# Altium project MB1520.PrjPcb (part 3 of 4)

## Sheet PoE.SchDoc: PoE
size A4; Date: Not used; ApprovedBy: Not used; CheckedBy: Not used; Author: Not used; CompanyName: STMicroelectronics; DrawnBy: Not used; Engineer: Not used; Organization: Not used; Address1: Not used; Address2: Not used; Address3: Not used; Address4: Not used; DocumentNumber: Not used; Revision: Not used; SheetNumber: 6; SheetTotal: 19
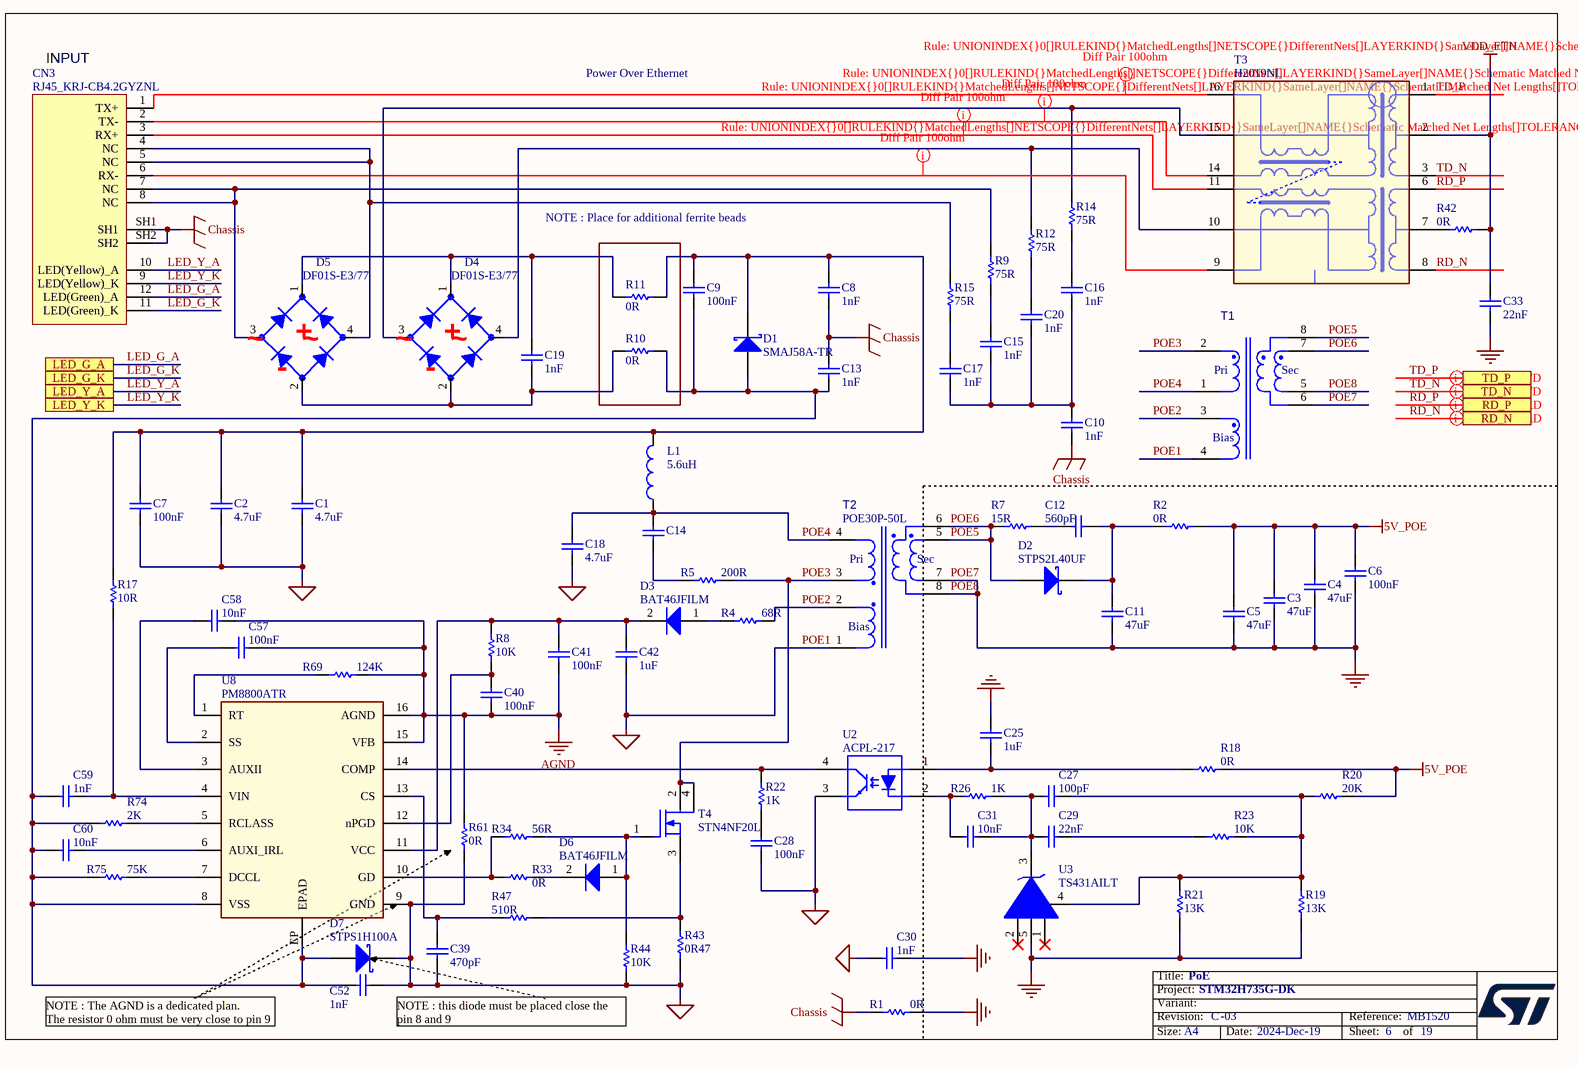
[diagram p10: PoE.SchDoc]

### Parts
C1  value 4.7uF  [C1210_H2P5]  (hidden comment: Capacitor)
C2  value 4.7uF  [C1210_H2P5]  (hidden comment: Capacitor)
C3  value 47uF  [C0805]  (hidden comment: Capacitor)
C4  value 47uF  [C0805]  (hidden comment: Capacitor)
C5  value 47uF  [C0805]  (hidden comment: Capacitor)
C6  value 100nF  [C0603]  (hidden comment: Capacitor)
C7  value 100nF  [C0805]  (hidden comment: Capacitor)
C8  value 1nF  [C0603]  (hidden comment: Capacitor)
C9  value 100nF  [C0805]  (hidden comment: Capacitor)
C10  value 1nF  [C1206_H1P6]  (hidden comment: Capacitor)
C11  value 47uF  [C0805]  (hidden comment: Capacitor)
C12  value 560pF  [C0603]  (hidden comment: Capacitor)
C13  value 1nF  [C0603]  (hidden comment: Capacitor)
C14  Capacitor  [C0603]  (value not drawn)
C15  value 1nF  [C0603]  (hidden comment: Capacitor)
C16  value 1nF  [C0603]  (hidden comment: Capacitor)
C17  value 1nF  [C0603]  (hidden comment: Capacitor)
C18  value 4.7uF  [C1210_H2P5]  (hidden comment: Capacitor)
C19  value 1nF  [C0603]  (hidden comment: Capacitor)
C20  value 1nF  [C0603]  (hidden comment: Capacitor)
C25  value 1uF  [C0603]  (hidden comment: Capacitor)
C27  value 100pF  [C0603]  (hidden comment: Capacitor)
C28  value 100nF  [C0603]  (hidden comment: Capacitor)
C29  value 22nF  [C0603]  (hidden comment: Capacitor)
C30  value 1nF  [C1206_H1P6]  (hidden comment: Capacitor)
C31  value 10nF  [C0603]  (hidden comment: Capacitor)
C33  value 22nF  [C0603]  (hidden comment: Capacitor)
C39  value 470pF  [C0603]  (hidden comment: Capacitor)
C40  value 100nF  [C0603]  (hidden comment: Capacitor)
C41  value 100nF  [C0603]  (hidden comment: Capacitor)
C42  value 1uF  [C0603]  (hidden comment: Capacitor)
C52  value 1nF  [C0603]  (hidden comment: Capacitor)
C57  value 100nF  [C0603]  (hidden comment: Capacitor)
C58  value 10nF  [C0603]  (hidden comment: Capacitor)
C59  value 1nF  [C0603]  (hidden comment: Capacitor)
C60  value 10nF  [C0603]  (hidden comment: Capacitor)
CN3  RJ45_KRJ-CB4.2GYZNL  [CON_RJ45_DGKYD_KRJ-CB4.2GYZNL]
D1  SMAJ58A-TR  [DIO_SMA_1A_2K]
D2  STPS2L40UF  [DIO_SMB-FLAT_1A_2K]
D3  value BAT46JFILM  [DIO_SOD323_1A_2K]  (hidden comment: DIODE_1A_2K)
D4  value DF01S-E3/77  [BRF_VISHAY_DFS_DF01S]  (hidden comment: DF01S_SMD)
D5  value DF01S-E3/77  [BRF_VISHAY_DFS_DF01S]  (hidden comment: DF01S_SMD)
D6  value BAT46JFILM  [DIO_SOD323_1A_2K]  (hidden comment: DIODE_1A_2K)
D7  value STPS1H100A  [DIO_SMA_DO214-AC_1A_2K]  (hidden comment: SMAJ58A-TR)
L1  value 5.6uH  [IND_POWER_COILCRAFT_ME3220]  (hidden comment: Inductor)
R1  value 0R  [R0805]  (hidden comment: Resistor)
R2  value 0R  [R0603]  (hidden comment: Resistor)
R4  value 68R  [R0805]  (hidden comment: Resistor)
R5  value 200R  [R1206_H0P55]  (hidden comment: Resistor)
R7  value 15R  [R0805]  (hidden comment: Resistor)
R8  value 10K  [R0603]  (hidden comment: Resistor)
R9  value 75R  [R0805]  (hidden comment: Resistor)
R10  value 0R  [R0805]  (hidden comment: Resistor)
R11  value 0R  [R0805]  (hidden comment: Resistor)
R12  value 75R  [R0805]  (hidden comment: Resistor)
R14  value 75R  [R0805]  (hidden comment: Resistor)
R15  value 75R  [R0805]  (hidden comment: Resistor)
R17  value 10R  [R0805]  (hidden comment: Resistor)
R18  value 0R  [R0805]  (hidden comment: Resistor)
R19  value 13K  [R0603]  (hidden comment: Resistor)
R20  value 20K  [R0603]  (hidden comment: Resistor)
R21  value 13K  [R0603]  (hidden comment: Resistor)
R22  value 1K  [R0603]  (hidden comment: Resistor)
R23  value 10K  [R0603]  (hidden comment: Resistor)
R26  value 1K  [R0603]  (hidden comment: Resistor)
R33  value 0R  [R0805]  (hidden comment: Resistor)
R34  value 56R  [R0805]  (hidden comment: Resistor)
R42  value 0R  [R0805]  (hidden comment: Resistor)
R43  value 0R47  [R1206_H0P55]  (hidden comment: Resistor)
R44  value 10K  [R0603]  (hidden comment: Resistor)
R47  value 510R  [R0603]  (hidden comment: Resistor)
R61  value 0R  [R0603]  (hidden comment: Resistor)
R69  value 124K  [R0603]  (hidden comment: Resistor)
R74  value 2K  [R0805]  (hidden comment: Resistor)
R75  value 75K  [R0603]  (hidden comment: Resistor)
T1  TRS_750315923  [TRS_WURTH_750315923]  (value not drawn)
T2  POE30P-50L  [TRS_COILCRAFT_POE30P-50L]
T3  H2019NL  [TRS_PULSE_H2019NL]
T4  STN4NF20L  [MOS_SOT223-TAB]
U2  value ACPL-217  [OPT_MINI-FLAT_FAIRCHILD_HMHA2801A]  (hidden comment: HMHA2801A)
U3  TS431AILT  [MOS_SOT23-5L]
U8  PM8800ATR  [ICC_HTSSOP16-EPAD_5X4P4_P065]

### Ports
LED_G_A, LED_G_K, LED_Y_A, LED_Y_K, RD_N, RD_P, TD_N, TD_P

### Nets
5V_POE: C3.2 C4.2 C5.2 C6.2 R2.2 R18.2 R20.2
AGND: C40.1 C41.1 C57.2 C58.2 R61.2 R69.2 U8.15(VFB) U8.16(AGND)
Chassis: C8.1 C10.1 C13.2 CN3.SH1 CN3.SH2 R1.1
POE1: C1.1 C2.1 C7.1 C18.1 C28.1 C30.1 C39.1 C42.1 C52.1 D7.2(K) R43.1 R44.1 R61.1 T1.4 T2.1 U2.3(Emitter) U8.9(GND)  [also labelled GND_POWER_IN]
POE7: C3.1 C4.1 C5.1 C6.1 C11.1 C25.2 C30.2 C33.1 R1.2 R19.2 R21.1 T1.5 T1.6 T2.7 T2.8 U3.5(A)  [also labelled GND, POE8]
VDD_ETH: C33.2 R42.2 T3.2(tct)
LED_G_A: CN3.12(LED(Green)_A) ; port LED_G_A
LED_G_K: CN3.11(LED(Green)_K) ; port LED_G_K
LED_Y_A: CN3.10(LED(Yellow)_A) ; port LED_Y_A
LED_Y_K: CN3.9(LED(Yellow)_K) ; port LED_Y_K
POE2: R4.2 T1.3 T2.2
POE3: R5.2 T1.2 T2.3 T4.2(D) T4.4(D)
POE4: C14.2 C18.2 L1.1 T1.1 T2.4
POE5: D2.1(A) R7.1 T1.7 T1.8 T2.5 T2.6  [also labelled POE6]
RD_N: T3.8(rd-) ; port RD_N
RD_P: T3.6(rd+) ; port RD_P
TD_N: T3.3(td-) ; port TD_N
TD_P: T3.1(td+) ; port TD_P
NetC1_2: C1.2 C2.2 C7.2 C8.2 C9.1 D1.2(K) L1.2 R11.2 R17.2
NetC9_2: C9.2 C13.1 C52.2 C59.2 C60.1 D1.1(A) D7.1(A) R10.2 R74.1 R75.1 U8.8(VSS) U8.EP(EPAD)
NetC10_2: C10.2 C15.1 C16.1 C17.1 C20.1
NetC11_2: C11.2 C12.2 D2.2(K) R2.1
NetC12_1: C12.1 R7.2
NetC14_1: C14.1 R5.1
NetC15_2: C15.2 R9.1
NetC16_2: C16.2 R14.1
NetC17_2: C17.2 R15.1
NetC19_1: C19.1 D4.2(DC_OUT_MINUS) D5.2(DC_OUT_MINUS) R10.1
NetC19_2: C19.2 D4.1(DC_OUT_PLUS) D5.1(DC_OUT_PLUS) R11.1
NetC20_2: C20.2 R12.1
NetC25_1: C25.1 R18.1 U2.1(Anode)
NetC27_1: C27.1 C29.1 C31.2 R26.1 U3.3(K)
NetC27_2: C27.2 R19.1 R20.1 R21.2 R23.1 U3.4(REF)
NetC28_2: C28.2 R22.1
NetC29_2: C29.2 R23.2
NetC31_1: C31.1 R26.2 U2.2(B)
NetC39_2: C39.2 R47.1 U8.13(CS)
NetC40_2: C40.2 R8.1 U8.12(nPGD)
NetC41_2: C41.2 C42.2 D3.2(K) R8.2 U8.11(VCC)
NetC57_1: C57.1 U8.2(SS)
NetC58_1: C58.1 U8.3(AUXII)
NetC59_1: C59.1 R17.1 U8.4(VIN)
NetC60_2: C60.2 U8.6(AUXI_IRL)
NetCN3_1: CN3.1(TX+) T3.16(tx1+)
NetCN3_2: CN3.2(TX-) T3.14(tx1-)
NetCN3_3: CN3.3(RX+) T3.11(rx1+)
NetCN3_4: CN3.4(NC) CN3.5(NC) D5.4(AC_IN_1) R15.2
NetCN3_6: CN3.6(RX-) T3.9(rx-)
NetCN3_7: CN3.7(NC) CN3.8(NC) D5.3(AC_IN_2) R9.2
NetD3_1: D3.1(A) R4.1
NetD4_3: D4.3(AC_IN_2) R14.2 T3.15(txct)
NetD4_4: D4.4(AC_IN_1) R12.2 T3.10(rxct)
NetD6_1: D6.1(A) R34.2 R44.2 T4.1(G)
NetD6_2: D6.2(K) R33.1
NetR22_2: R22.2 U2.4(Collector) U8.14(COMP)
NetR33_2: R33.2 R34.1 U8.10(GD)
NetR42_1: R42.1 T3.7(rct)
NetR43_2: R43.2 R47.2 T4.3(S)
NetR69_1: R69.1 U8.1(RT)
NetR74_2: R74.2 U8.5(RCLASS)
NetR75_2: R75.2 U8.7(DCCL)

Not connected (* = marked no-connect by the designer): U3 1(NC)* 2(NC)*

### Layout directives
differential pair: RD_N, RD_P, TD_N, TD_P
rule Matched Net Lengths [Tolerance = 100mil]: NetCN3_1, NetCN3_2, NetCN3_3, NetCN3_6

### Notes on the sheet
- INPUT
- Power Over Ethernet
- NOTE : Place for additional ferrite beads
- NOTE : The AGND is a dedicated plan.
  The resistor 0 ohm must be very close to pin 9
- NOTE : this diode must be placed close the pin 8 and 9

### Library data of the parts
C1 C2 C18 = MCD-02212: Capacitor, MLCC, 4.7uF, 100V, X7S, +/-10%, 1210, T=2mm; Manufacturer_Part_Number: CGA6M3X7S2A475K200AB; Manufacturer: TDK; Part_Preference: Recommended; Component_Country_Of_Origin: Unknown; ID: 4312; Order_Code_RS: 111-0119; ShowFields: YES
C3-C5 C11 = MCD-00204: Capacitor, MLCC, 47uF, 10V, X5R, 20%, 0805, T=1,25mm; Manufacturer_Part_Number: GRM21BR61A476ME15K; Manufacturer: MURATA; Part_Preference: Recommended; Provided_By: SUBCO; Component_Country_Of_Origin: Japan; ID: 2664; ShowFields: YES
C6 = MCD-00211: Capacitor, MLCC, 100nF, 16V, X7R, 10%, 0603, T=0,8mm; Manufacturer_Part_Number: CC0603KRX7R7BB104; Manufacturer: YAGEO; Part_Preference: Recommended; Provided_By: SUBCO; Component_Country_Of_Origin: China; ID: 2659; Order_Code_RS: 669-8763; ShowFields: YES
C7 C9 = MCD-01093: Capacitor,100nF,100V,X7R,10%,0805; Manufacturer_Part_Number: C2012X7R2A104K125AA; Manufacturer: TDK; Part_Preference: Recommended; Provided_By: SUBCO; Component_Country_Of_Origin: Unknown; ID: 3402; Order_Code_RS: 921-4157; ShowFields: YES
C8 C13 C15-C17 C19 C20 C52 C59 = MCD-01091: Capacitor,1nF,100V,X7R,10%,0603; Manufacturer_Part_Number: CC0603KRX7R0BB102; Manufacturer: YAGEO; Part_Preference: Recommended; Provided_By: SUBCO; Component_Country_Of_Origin: China; ID: 3403; Order_Code_RS: 669-9000; ShowFields: YES
C10 C30 = MCD-00722: Capacitor, MLCC, 1nF, 2KV, X7R, 10%, 1206, T=1,25mm; Manufacturer_Part_Number: CC1206KKX7RDBB102; Manufacturer: YAGEO; Part_Preference: Recommended; Provided_By: SUBCO; Component_Country_Of_Origin: China; ID: 3027; ShowFields: YES
C12 = MCD-01095: Capacitor,560pF,16V,X7R,10%,0603; Manufacturer_Part_Number: 0603YC561KAT2A; Manufacturer: AVX; Part_Preference: Recommended; Provided_By: SUBCO; Component_Country_Of_Origin: China; ID: 3400; ShowFields: YES
C14 = MCD-01096: Capacitor,27pF,100V,NPO,5%,0603; Manufacturer_Part_Number: CC0603JRNPO0BN270; Manufacturer: YAGEO; Part_Preference: Recommended; Provided_By: SUBCO; Component_Country_Of_Origin: China; ID: 3394; ShowFields: YES
C25 C42 = MCD-01100: Capacitor,1uF,25V,X5R,10%,0603; Manufacturer_Part_Number: CC0603KRX5R8BB105; Manufacturer: YAGEO; BMS_Part_Number: 9142279; Part_Preference: Recommended; Provided_By: SUBCO; Component_Country_Of_Origin: China; ID: 3398; ShowFields: YES
C27 = MCD-01101: Capacitor,100pF,50V,X7R,10%,0603; Manufacturer_Part_Number: 06035C101JAT4A; Manufacturer: AVX; Part_Preference: Recommended; Provided_By: SUBCO; Component_Country_Of_Origin: China; ID: 3399; ShowFields: YES
C28 C40 C41 C57 = MCD-01099: Capacitor,100nF,50V,X7R,10%,0603; Manufacturer_Part_Number: CC0603KRX7R9BB104; Manufacturer: YAGEO; BMS_Part_Number: 9142278; Part_Preference: Recommended; Provided_By: SUBCO; Component_Country_Of_Origin: China; ID: 3397; Order_Code_RS: 669-8767; ShowFields: YES
C29 C33 = MCD-01103: Capacitor,22nF,50V,X7R,10%,0603; Manufacturer_Part_Number: CC0603KRX7R9BB223; Manufacturer: YAGEO; BMS_Part_Number: 9142231; Part_Preference: Recommended; Provided_By: SUBCO; Component_Country_Of_Origin: China; ID: 3390; ShowFields: YES
C31 = MCD-00017: Capacitor, MLCC, 10nF, 50V, X7R, +/-10%, 0603, T=0.8mm; Manufacturer_Part_Number: CC0603KRX7R9BB103; Manufacturer: YAGEO; Part_Preference: Recommended; Component_Country_Of_Origin: China; ID: 2500; Order_Code_RS: 722236; ShowFields: YES
C39 = MCD-01104: Capacitor,470pF,100V,X7R,10%,0603; Manufacturer_Part_Number: 06031C471KAT2A; Manufacturer: AVX; Part_Preference: Recommended; Provided_By: SUBCO; Component_Country_Of_Origin: China; ID: 3393; Order_Code_RS: 888-2112; ShowFields: YES
C58 C60 = MCD-01098: Capacitor,10nF,100V,X7R,10%,0603; Manufacturer_Part_Number: CC0603KRX7R0BB103; Manufacturer: YAGEO; Part_Preference: Recommended; Provided_By: SUBCO; Component_Country_Of_Origin: China; ID: 3396; ShowFields: YES
CN3 = MCD-00717: RJ45 jack, single port, with LEDS, Metal shielded dip low profile; Part_Type: Connector; Manufacturer: DONGGUAN KEYOUDA ELECTRONIC TECHNOLOGY; Part_Preference: Recommended; Provided_By: SUBCO; Component_Country_Of_Origin: Unknown; ID: 3029; ShowFields: YES
D1 = MCD-01083: Transil 400W, VRM=58V; Part_Type: Diode; Manufacturer: STMICROELECTRONICS; BMS_Part_Number: 9151124; Manufacturer_HQ_COO: EU; Part_Preference: Recommended; Provided_By: SUBCO with ST control; Component_Country_Of_Origin: China; ID: 3407; Order_Code_RS: 168-6873; ShowFields: YES
D2 = MCD-01087: Low drop power Schottky rectifier(2A, 40V, 0.34V); Part_Type: Diode; Manufacturer: STMICROELECTRONICS; BMS_Part_Number: 9151009; Manufacturer_HQ_COO: EU; Part_Preference: Recommended; Provided_By: SUBCO with ST control; Component_Country_Of_Origin: China; ID: 3406; Order_Code_RS: 189-3975; ShowFields: YES
D3 D6 = MCD-01064: Schottky Single diode,150mA, 100V; Manufacturer: STMICROELECTRONICS; BMS_Part_Number: 9151125; Manufacturer_HQ_COO: EU; Part_Preference: Recommended; Provided_By: SUBCO with ST control; Component_Country_Of_Origin: China; ID: 3424; ShowFields: YES
D4 D5 = MCD-02211: Surface Mount Bridge Rectifier 1A 100V; Part_Type: IC; Part_Preference: Recommended; Manufacturer: VISHAY; Component_Country_Of_Origin: China; ShowFields: YES; ID: 4311
D7 = MCD-01165: High voltage power Schottky rectifier; Part_Type: Diode; Manufacturer: STMICROELECTRONICS; BMS_Part_Number: 9151102; Manufacturer_HQ_COO: EU; Part_Preference: Recommended; Provided_By: SUBCO with ST control; Component_Country_Of_Origin: China; ID: 3327; Order_Code_RS: 249-892; ShowFields: YES
L1 = MCD-01109: Power Inductor, 5.6uH, 0.2R, ME3220-562ML; Manufacturer: COILCRAFT; Part_Preference: Recommended; Provided_By: SUBCO; Component_Country_Of_Origin: Unknown; ID: 3389; ShowFields: YES
R1 R10 R11 R18 R33 R42 = MCD-00179: Resistor,0R,0805,5%; Manufacturer_Part_Number: RC0805JR-070RL; Manufacturer: YAGEO; Part_Preference: Recommended; Provided_By: SUBCO; Component_Country_Of_Origin: China; ID: 2685; ShowFields: YES
R2 R61 = MCD-00056: Resistor,0R,0603,5%,1/10W; Manufacturer_Part_Number: RC0603JR-070RL; Manufacturer: YAGEO; Part_Preference: Recommended; Provided_By: SUBCO; Component_Country_Of_Origin: China; ID: 2536; ShowFields: YES
R4 = MCD-01115: Resistor,68R,0805,1%; Manufacturer_Part_Number: RC0805FR-0768RL; Manufacturer: YAGEO; Part_Preference: Recommended; Provided_By: SUBCO; Component_Country_Of_Origin: China; ID: 3379; ShowFields: YES
R5 = MCD-01114: Resistor,200R,1206,1%; Manufacturer_Part_Number: LTR18EZPF2000; Manufacturer: ROHM SEMICONDUCTOR; Part_Preference: Recommended; Provided_By: SUBCO; Component_Country_Of_Origin: Philippines, Thailand; ID: 3381; ShowFields: YES
R7 = MCD-01113: Resistor,15R,0805,1%; Manufacturer_Part_Number: RC0805FR-0715RL; Manufacturer: YAGEO; Part_Preference: Recommended; Provided_By: SUBCO; Component_Country_Of_Origin: China; ID: 3383; Order_Code_RS: 618-3476; ShowFields: YES
R8 R23 R44 = MCD-00220: Resistor,10K,0603,1%,1/10W; Manufacturer_Part_Number: RC0603FR-0710KL; Manufacturer: YAGEO; Part_Preference: Recommended; Provided_By: SUBCO; Component_Country_Of_Origin: China; ID: 2649; ShowFields: YES
R9 R12 R14 R15 = MCD-01112: Resistor,75R,0805,1%; Manufacturer_Part_Number: RC0805FR-0775RL; Manufacturer: YAGEO; Part_Preference: Recommended; Provided_By: SUBCO; Component_Country_Of_Origin: China; ID: 3380; ShowFields: YES
R17 = MCD-01111: Resistor,10R,0805,1%,Stackpole,1/4W; Manufacturer_Part_Number: RNCP0805FTD10R0; Part_Preference: Recommended; Provided_By: SUBCO; Component_Country_Of_Origin: Taiwan; ID: 3385; ShowFields: YES
R19 R21 = MCD-00384: Resistor,13K,0603,1%,1/10W; Manufacturer_Part_Number: RC0603FR-0713KL; Manufacturer: YAGEO; Part_Preference: Recommended; Provided_By: SUBCO; Component_Country_Of_Origin: China; ID: 2894; ShowFields: YES
R20 = MCD-00422: Resistor,20K,0603,1%,1/10W; Manufacturer_Part_Number: RC0603FR-0720KL; Manufacturer: YAGEO; Part_Preference: Recommended; Provided_By: SUBCO; Component_Country_Of_Origin: China; ID: 2854; ShowFields: YES
R22 R26 = MCD-00070: Resistor,1K,0603,1%,1/10W; Manufacturer_Part_Number: RC0603FR-071KL; Manufacturer: YAGEO; Part_Preference: Recommended; Provided_By: SUBCO; Component_Country_Of_Origin: China; ID: 2522; ShowFields: YES
R34 = MCD-01118: Resistor,56R,0805,1%; Manufacturer_Part_Number: RC0805FR-0756RL; Manufacturer: YAGEO; Part_Preference: Recommended; Provided_By: SUBCO; Component_Country_Of_Origin: China; ID: 3376; ShowFields: YES
R43 = MCD-01119: Resistor,0.47R,1206,1%; Manufacturer_Part_Number: RL1206FR-070R47L; Manufacturer: YAGEO; Part_Preference: Recommended; Provided_By: SUBCO; Component_Country_Of_Origin: Taiwan; ID: 3382; ShowFields: YES
R47 = MCD-00225: Resistor,510R,0603,1%,1/10W; Manufacturer_Part_Number: RC0603FR-07510RL; Manufacturer: YAGEO; Part_Preference: Recommended; Provided_By: SUBCO; Component_Country_Of_Origin: China; ID: 2644; ShowFields: YES
R69 = MCD-01116: Resistor,124K,0603,1%; Manufacturer_Part_Number: RC0603FR-07124KL; Manufacturer: YAGEO; Part_Preference: Recommended; Provided_By: SUBCO; Component_Country_Of_Origin: China; ID: 3377; ShowFields: YES
R74 = MCD-01117: Resistor,2K,0805,1%; Manufacturer_Part_Number: RC0805FR-072KL; Manufacturer: YAGEO; Part_Preference: Recommended; Provided_By: SUBCO; Component_Country_Of_Origin: China; ID: 3378; ShowFields: YES
R75 = MCD-00522: Resistor,75K,0603,1%,1/10W; Manufacturer_Part_Number: RC0603FR-0775KL; Manufacturer: YAGEO; Part_Preference: Recommended; Provided_By: SUBCO; Component_Country_Of_Origin: China; ID: 3221; ShowFields: YES
T1 = MCD-01063: Flyback Transformers for 3 Watt, PoE applications; Part_Type: IC; Manufacturer: WURTH ELEKTRONIK; Part_Preference: Recommended; Provided_By: SUBCO; Component_Country_Of_Origin: Unknown; ID: 3426; ShowFields: YES
T2 = MCD-01081: Flyback Transformers for 3 Watt, PoE applications, CoilCraft Cyntec; Part_Type: IC; Part_Preference: Recommended; Provided_By: SUBCO; Component_Country_Of_Origin: Unknown; ID: 3409; ShowFields: YES
T3 = MCD-01067: 10/100BASE-TX VoIP Magnetics Modules, Data Transformer; Part_Type: IC; Manufacturer: PULSE ELECTRONICS; Part_Preference: Recommended; Provided_By: SUBCO; Component_Country_Of_Origin: China; ID: 3423; ShowFields: YES
T4 = MCD-01086: Annel 200 V, 1.1ohm, 1 A, low gate charge STripFET II, Power MOSFET; Part_Type: IC; Manufacturer: STMICROELECTRONICS; BMS_Part_Number: 9153018; Manufacturer_HQ_COO: EU; Part_Preference: Recommended; Provided_By: SUBCO with ST control; Component_Country_Of_Origin: China; ID: 3405; ShowFields: YES
U2 = MCD-03054: IC, Half-Pitch Phototransistor Optocoupler, DC Input, 3750V, 4-pin SO; Manufacturer_Part_Number: ACPL-217-560E; Manufacturer: BROADCOM LIMITED; Part_Preference: Recommended; Component_Country_Of_Origin: Singapore°; ID: 5170; ShowFields: YES
U3 = MCD-01089: Low voltage adjustable shunt reference; Part_Type: IC; Manufacturer: STMICROELECTRONICS; BMS_Part_Number: 9177032; Manufacturer_HQ_COO: EU; Part_Preference: Recommended; Provided_By: SUBCO with ST control; Component_Country_Of_Origin: Malaysia; ID: 3404; Order_Code_RS: 145-8772; ShowFields: YES
U8 = MCD-01080: Integrated IEEE 802.3af compliant PoE-PD interface, and PWM controller with support of external source; Part_Type: IC; Manufacturer: STMICROELECTRONICS; BMS_Part_Number: 9177966; Manufacturer_HQ_COO: EU; Part_Preference: Recommended; Provided_By: SUBCO with ST control; Component_Country_Of_Origin: Philippines; ID: 3410; ShowFields: YES

## Sheet FDCAN.SchDoc: FDCAN
size A4; Date: Not used; ApprovedBy: Not used; CheckedBy: Not used; Author: Not used; CompanyName: STMicroelectronics; DrawnBy: Not used; Engineer: Not used; Organization: Not used; Address1: Not used; Address2: Not used; Address3: Not used; Address4: Not used; DocumentNumber: Not used; Revision: Not used; SheetNumber: 8; SheetTotal: 19
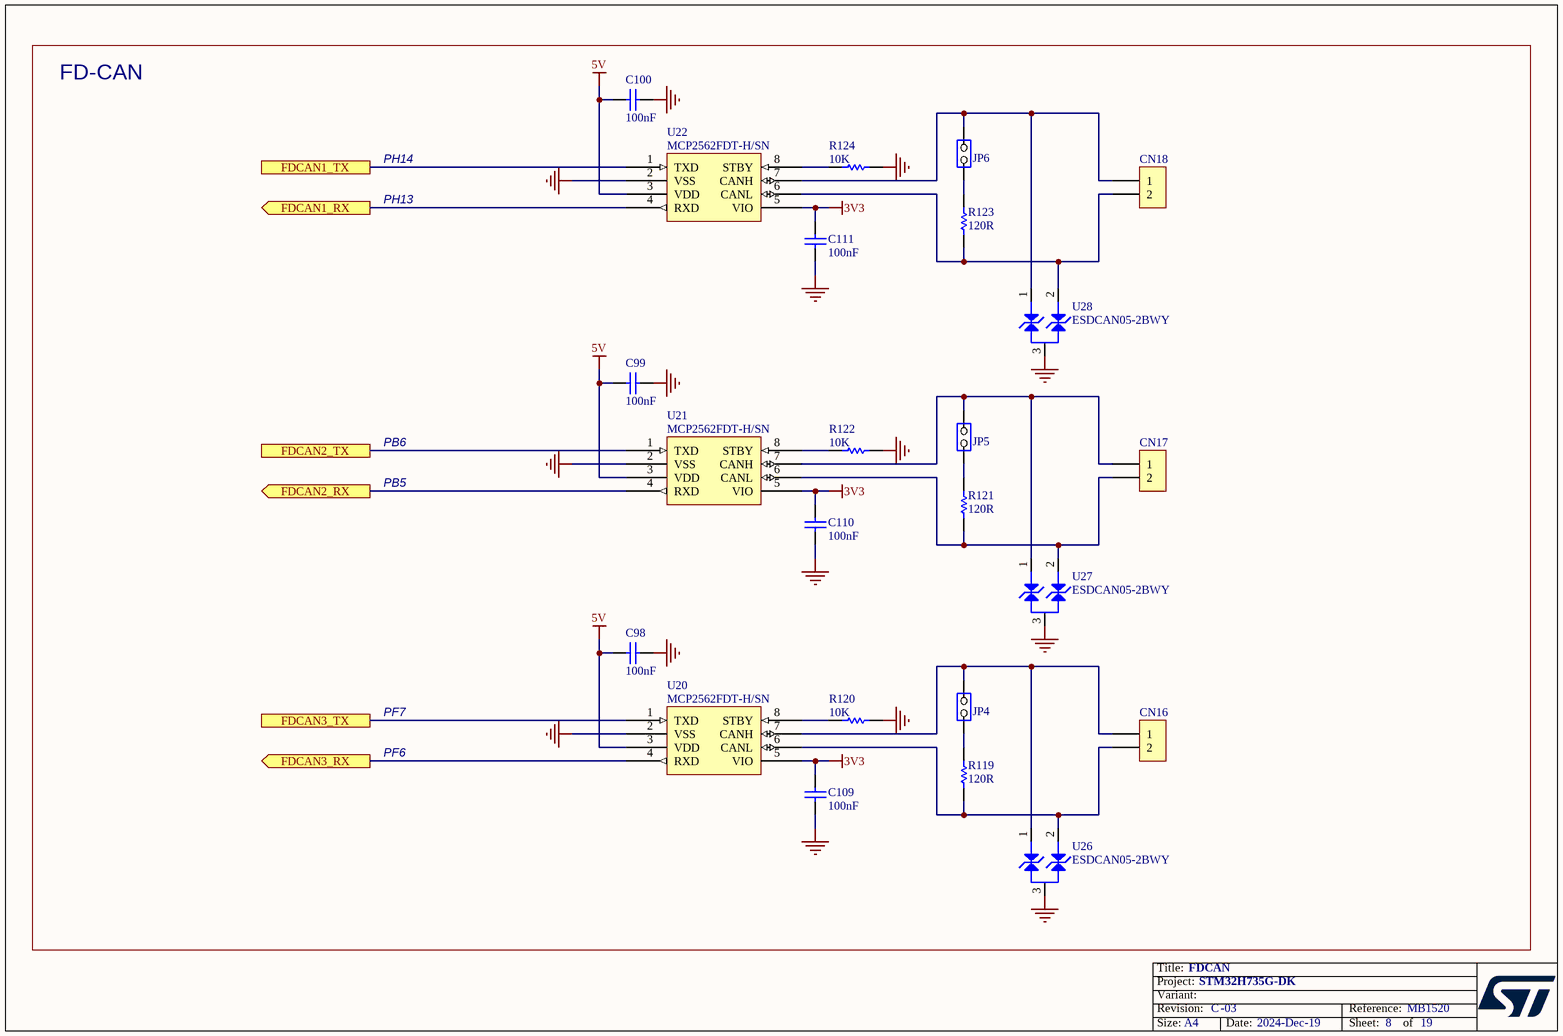
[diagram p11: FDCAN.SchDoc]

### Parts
C98  value 100nF  [C0402]  (hidden comment: Capacitor)
C99  value 100nF  [C0402]  (hidden comment: Capacitor)
C100  value 100nF  [C0402]  (hidden comment: Capacitor)
C109  value 100nF  [C0402]  (hidden comment: Capacitor)
C110  value 100nF  [C0402]  (hidden comment: Capacitor)
C111  value 100nF  [C0402]  (hidden comment: Capacitor)
CN16  Header 2x1  [CON_988-JIUBABA_PHFS25-11-02-G0B115-T-1]  (value not drawn)
CN17  Header 2x1  [CON_988-JIUBABA_PHFS25-11-02-G0B115-T-1]  (value not drawn)
CN18  Header 2x1  [CON_988-JIUBABA_PHFS25-11-02-G0B115-T-1]  (value not drawn)
JP4  Jumper_Header 2x1  [CON_SAMTEC_TSW-102-07-G-S]  (value not drawn)
JP5  Jumper_Header 2x1  [CON_SAMTEC_TSW-102-07-G-S]  (value not drawn)
JP6  Jumper_Header 2x1  [CON_SAMTEC_TSW-102-07-G-S]  (value not drawn)
R119  value 120R  [R0402]  (hidden comment: Resistor)
R120  value 10K  [R0402]  (hidden comment: Resistor)
R121  value 120R  [R0402]  (hidden comment: Resistor)
R122  value 10K  [R0402]  (hidden comment: Resistor)
R123  value 120R  [R0402]  (hidden comment: Resistor)
R124  value 10K  [R0402]  (hidden comment: Resistor)
U20  value MCP2562FDT-H/SN  [ICC_SO8_5X4_P127]  (hidden comment: MCP2562FD)
U21  value MCP2562FDT-H/SN  [ICC_SO8_5X4_P127]  (hidden comment: MCP2562FD)
U22  value MCP2562FDT-H/SN  [ICC_SO8_5X4_P127]  (hidden comment: MCP2562FD)
U26  value ESDCAN05-2BWY  [DIO_SOT323]  (hidden comment: ESD-TRANSIL-DUAL-BIDIR)
U27  value ESDCAN05-2BWY  [DIO_SOT323]  (hidden comment: ESD-TRANSIL-DUAL-BIDIR)
U28  value ESDCAN05-2BWY  [DIO_SOT323]  (hidden comment: ESD-TRANSIL-DUAL-BIDIR)

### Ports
FDCAN1_RX (out), FDCAN1_TX, FDCAN2_RX (out), FDCAN2_TX, FDCAN3_RX (out), FDCAN3_TX

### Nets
3V3: C109.2 C110.2 C111.2 U20.5(VIO) U21.5(VIO) U22.5(VIO)
5V: C98.2 C99.2 C100.2 U20.3(VDD) U21.3(VDD) U22.3(VDD)
GND: C98.1 C99.1 C100.1 C109.1 C110.1 C111.1 R120.2 R122.2 R124.2 U20.2(VSS) U21.2(VSS) U22.2(VSS) U26.3 U27.3 U28.3  [project net POE7]
FDCAN1_RX: U22.4(RXD) ; port FDCAN1_RX
FDCAN1_TX: U22.1(TXD) ; port FDCAN1_TX
FDCAN2_RX: U21.4(RXD) ; port FDCAN2_RX
FDCAN2_TX: U21.1(TXD) ; port FDCAN2_TX
FDCAN3_RX: U20.4(RXD) ; port FDCAN3_RX
FDCAN3_TX: U20.1(TXD) ; port FDCAN3_TX
NetCN16_1: CN16.1 JP4.2(NO) U20.7(CANH) U26.1
NetCN16_2: CN16.2 R119.1 U20.6(CANL) U26.2
NetCN17_1: CN17.1 JP5.2(NO) U21.7(CANH) U27.1
NetCN17_2: CN17.2 R121.1 U21.6(CANL) U27.2
NetCN18_1: CN18.1 JP6.2(NO) U22.7(CANH) U28.1
NetCN18_2: CN18.2 R123.1 U22.6(CANL) U28.2
NetJP4_1: JP4.1(COMMON) R119.2
NetJP5_1: JP5.1(COMMON) R121.2
NetJP6_1: JP6.1(COMMON) R123.2
NetR120_1: R120.1 U20.8(STBY)
NetR122_1: R122.1 U21.8(STBY)
NetR124_1: R124.1 U22.8(STBY)

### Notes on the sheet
- FD-CAN
- PH14
- PH13
- PB6
- PB5
- PF7
- PF6

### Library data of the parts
C98-C100 C109-C111 = MCD-00006: Capacitor, MLCC, 100nF, 16V, X7R, +/-10%, 0402, T=0.5mm; Manufacturer_Part_Number: CC0402KRX7R7BB104; Manufacturer: YAGEO; Part_Preference: Recommended; Partial_Alternate_Internal_Part_Number: MCD-03299; Component_Country_Of_Origin: China; ID: 2474; Order_Code_RS: 9402047; ShowFields: YES
CN16-CN18 = MCD-00314: Header, 2x1, 2.54mm, VR, TH, Height 6mm/3mm; Part_Type: Connector; Manufacturer_Part_Number: PHFS25-11-02-G0B115-T-1; Manufacturer: JIUBABA; Part_Preference: Alternate; Provided_By: SUBCO; Alternate_EMS: A; Component_Country_Of_Origin: Unknown; ID: 2554; ShowFields: YES
JP4-JP6 = MCD-00045: Header, 2x1, 2,54mm, VR, TH, Height 5.84mm/2.54mm; Manufacturer_Part_Number: TSW-102-07-G-S; Manufacturer: SAMTEC; Part_Type: Connector; Alternate_Manufacturer_Part_Number: 313102S111116; Alternate_Manufacturer: JIUBABA; Full_Alternate_Internal_Part_Number: MCD-02390; Part_Preference: Recommended; Partial_Alternate_Internal_Part_Number: MCD-02957; Provided_By: SUBCO; Alternate_EMS: A; Component_Country_Of_Origin: China, Costa Rica, Malaysia, United States, Vietnam; ID: 2545; Order_Code_RS: 155-5312; ShowFields: YES
R119 R121 R123 = MCD-00194: Resistor, 120R, 0402, +/-1%, 1/16W; Manufacturer_Part_Number: RC0402FR-07120RL; Manufacturer: YAGEO; Part_Preference: Recommended; Component_Country_Of_Origin: China; ID: 2674; ShowFields: YES
R120 R122 R124 = MCD-00053: Resistor,10K,0402,1%,1/16W; Manufacturer_Part_Number: RC0402FR-0710KL; Manufacturer: YAGEO; BMS_Part_Number: 9131590; Part_Preference: Recommended; Provided_By: SUBCO; Component_Country_Of_Origin: China; ID: 2539; ShowFields: YES
U20-U22 = MCD-00129: High-Speed CAN Flexible Data Rate Transceiver; Part_Type: IC; Manufacturer: MICROCHIP; Part_Preference: Recommended; Provided_By: SUBCO; Component_Country_Of_Origin: Unknown; ID: 2737; ShowFields: YES
U26-U28 = MCD-01358: Automotive dual-line Transil, transient voltage suppressor (TVS) for CAN bus 36V. Compliant with interfaces in automotive: CAN-FD, LIN, FlexRay, MOST, SENT, USB; Part_Type: Diode; Manufacturer: STMICROELECTRONICS; BMS_Part_Number: 9179021; Manufacturer_HQ_COO: EU; Part_Preference: Recommended; ECCN_US: EAR99; ECCN_EU: NEC; Provided_By: SUBCO with ST control; Component_Country_Of_Origin: China; ID: 3458; ShowFields: YES

## Sheet STlink_V3E_Module.SchDoc: ST-LINK/V3E-SWD Module
size A4; Date: Not used; ApprovedBy: Not used; CheckedBy: Not used; Author: Not used; CompanyName: STMicroelectronics; DrawnBy: Not used; Engineer: Not used; Organization: Not used; Address1: Not used; Address2: Not used; Address3: Not used; Address4: Not used; DocumentNumber: Not used; Revision: Not used; SheetNumber: 17; SheetTotal: 19
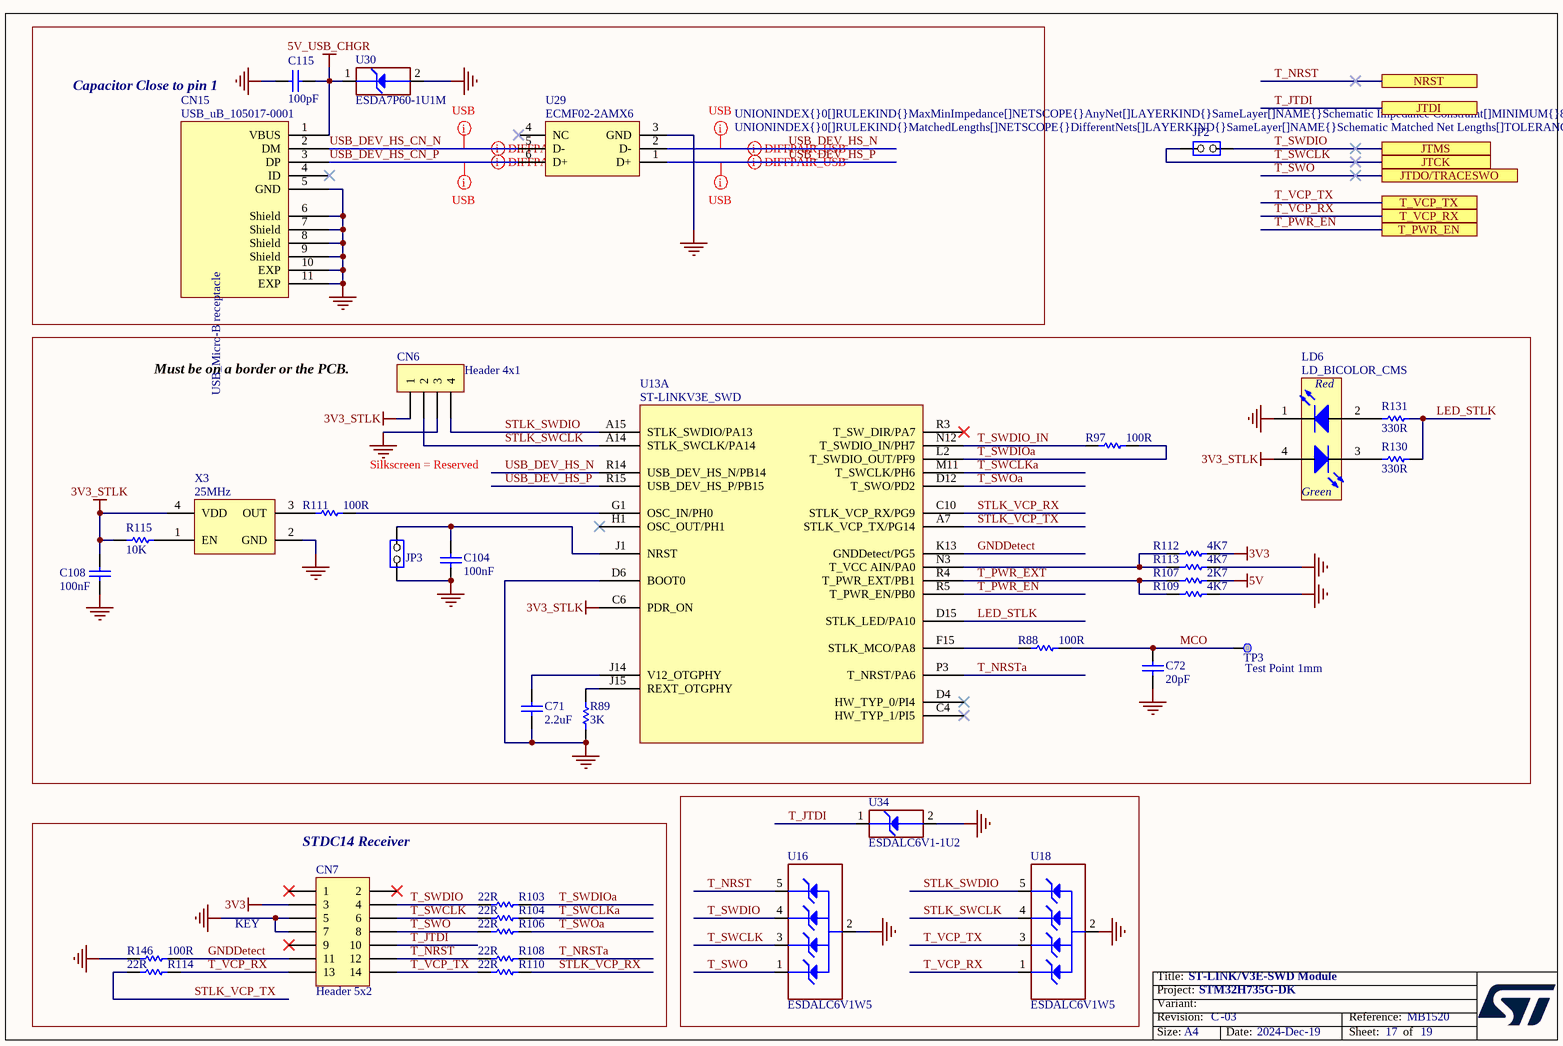
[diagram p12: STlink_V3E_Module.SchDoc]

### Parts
C71  value 2.2uF  [C0603]  (hidden comment: Capacitor)
C72  value 20pF  [C0402]  (hidden comment: Capacitor)
C104  value 100nF  [C0402]  (hidden comment: Capacitor)
C108  value 100nF  [C0402]  (hidden comment: Capacitor)
C115  value 100pF  [C0402]  (hidden comment: Capacitor)
CN6  Header 4x1  [CON_SAMTEC_TSW-104-07-G-S]
CN7  value Header 5x2  [CON_STDC14_Receiver_MEDIUM_WITH_MIPI10_3D]  (hidden comment: Header 7x2)
CN15  value USB_uB_105017-0001  [CON_USBMICROB_MOLEX_105017-0001_H2P90]  (hidden comment: USB_uB_105017.0001)
JP2  Jumper_Header 2x1  [CON_SAMTEC_TSW-102-07-G-S]  (value not drawn)
JP3  Jumper_Header 2x1  [CON_SAMTEC_TSW-102-07-G-S]  (value not drawn)
LD6  LD_BICOLOR_CMS  [LED_BI-GR_HSMF-A201-A00J1]
R88  value 100R  [R0402]  (hidden comment: Resistor)
R89  value 3K  [R0402]  (hidden comment: Resistor)
R97  value 100R  [R0402]  (hidden comment: Resistor)
R103  value 22R  [R0402]  (hidden comment: Resistor)
R104  value 22R  [R0402]  (hidden comment: Resistor)
R106  value 22R  [R0402]  (hidden comment: Resistor)
R107  value 2K7  [R0402]  (hidden comment: Resistor)
R108  value 22R  [R0402]  (hidden comment: Resistor)
R109  value 4K7  [R0402]  (hidden comment: Resistor)
R110  value 22R  [R0402]  (hidden comment: Resistor)
R111  value 100R  [R0402]  (hidden comment: Resistor)
R112  value 4K7  [R0402]  (hidden comment: Resistor)
R113  value 4K7  [R0402]  (hidden comment: Resistor)
R114  value 22R  [R0402]  (hidden comment: Resistor)
R115  value 10K  [R0402]  (hidden comment: Resistor)
R130  value 330R  [R0603]  (hidden comment: Resistor)
R131  value 330R  [R0603]  (hidden comment: Resistor)
R146  value 100R  [R0402]  (hidden comment: Resistor)
TP3  value Test Point 1mm  [TP_SMD_1MM]  (hidden comment: Test Point)  (no BOM)
U13  ST-LINKV3E_SWD  [ICC_UFBGA201_176+25_10X10_P065]  (part A of 2)
U16  ESDALC6V1W5  [ESD_SOT323-5L]
U18  ESDALC6V1W5  [ESD_SOT323-5L]
U29  ECMF02-2AMX6  [ESD_QFN-6L_1P7X1P5_P050]
U30  value ESDA7P60-1U1M  [ESD_QFN2_1P6X1_P125]  (hidden comment: ESD-TRANSIL)
U34  value ESDALC6V1-1U2  [ESD_ST0201]  (hidden comment: ESD-TRANSIL)
X3  value 25MHz  [OSC_NDK_NZ2520SB_4P]  (hidden comment: OSCILLATOR_4_PINS)

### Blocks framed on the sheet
Capacitor Close to pin 1: C115 CN15 U29 U30
Must be on a border or the PCB.: C71 C72 C104 C108 CN6 JP3 LD6 R88 R89 R97 R107 R109 R111-R113 R115 R130 R131 TP3 U13 X3
STDC14 Receiver: CN7 R103 R104 R106 R108 R110 R114 R146

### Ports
JTCK, JTDI, JTDO/TRACESWO, JTMS, NRST, T_PWR_EN, T_VCP_RX, T_VCP_TX

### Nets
3V3: CN7.3 R112.2
3V3_STLK: C108.2 CN6.1 LD6.4(YellowGreen_anode) R115.1 U13.C6(PDR_ON) X3.4(VDD)
5V: R107.1
5V_USB_CHGR: C115.2 CN15.1(VBUS) U30.1(IO1)
GND: C71.1 C72.1 C104.1 C108.1 C115.1 CN6.3 CN7.5 CN7.7 CN15.5(GND) CN15.6(Shield) CN15.7(Shield) CN15.8(Shield) CN15.9(Shield) CN15.10(EXP) CN15.11(EXP) JP3.1(COMMON) LD6.1(RED_cathode) R89.1 R109.1 R113.2 R146.1 U13.D6(BOOT0) U16.2(GND) U18.2(GND) U29.3(GND) U30.2(GND) U34.2(GND) X3.2(GND)  [project net POE7]
GNDDetect: CN7.11 R146.2 U13.K13(GNDDetect/PG5)
LED_STLK: R130.2 R131.2 U13.D15(STLK_LED/PA10)
MCO: C72.2 R88.2 TP3.1
STLK_SWCLK: CN6.2 U13.A14(STLK_SWCLK/PA14) U18.4(IO3)
STLK_SWDIO: CN6.4 U13.A15(STLK_SWDIO/PA13) U18.5(IO4)
STLK_VCP_RX: R110.2 U13.C10(STLK_VCP_RX/PG9)
STLK_VCP_TX: R114.1 U13.A7(STLK_VCP_TX/PG14)
T_JTDI: CN7.10 U34.1(IO1) ; port JTDI
T_NRST: CN7.12 R108.1 U16.5(IO4) ; port NRST  [project net RESET]
T_NRSTa: R108.2 U13.P3(T_NRST/PA6)
T_PWR_EN: U13.R5(T_PWR_EN/PB0) ; port T_PWR_EN
T_PWR_EXT: R107.2 R109.2 U13.R4(T_PWR_EXT/PB1)
T_SWCLK: CN7.6 JP2.1(COMMON) R104.1 U16.3(IO2) ; port JTCK
T_SWCLKa: R104.2 U13.M11(T_SWCLK/PH6)
T_SWDIO: CN7.4 JP2.2(NO) R103.1 U16.4(IO3) ; port JTMS
T_SWDIO_IN: R97.1 U13.N12(T_SWDIO_IN/PH7)
T_SWDIOa: R97.2 R103.2 U13.L2(T_SWDIO_OUT/PF9)
T_SWO: CN7.8 R106.1 U16.1(IO1) ; port JTDO/TRACESWO
T_SWOa: R106.2 U13.D12(T_SWO/PD2)
T_VCP_RX: CN7.13 R114.2 U18.1(IO1) ; port T_VCP_RX
T_VCP_TX: CN7.14 R110.1 U18.3(IO2) ; port T_VCP_TX
USB_DEV_HS_CN_N: CN15.2(DM) U29.5(D-)
USB_DEV_HS_CN_P: CN15.3(DP) U29.6(D+)
USB_DEV_HS_N: U13.R14(USB_DEV_HS_N/PB14) U29.2(D-)
USB_DEV_HS_P: U13.R15(USB_DEV_HS_P/PB15) U29.1(D+)
NetC71_2: C71.2 U13.J14(V12_OTGPHY)
NetC104_2: C104.2 JP3.2(NO) U13.J1(NRST)
NetLD6_2: LD6.2(Red_anode) R131.1
NetLD6_3: LD6.3(YellowGreen_cathode) R130.1
NetR88_1: R88.1 U13.F15(STLK_MCO/PA8)
NetR89_2: R89.2 U13.J15(REXT_OTGPHY)
NetR111_1: R111.1 X3.3(OUT)
NetR111_2: R111.2 U13.G1(OSC_IN/PH0)
NetR112_1: R112.1 R113.1 U13.N3(T_VCC_AIN/PA0)
NetR115_2: R115.2 X3.1(EN)

Not connected (* = marked no-connect by the designer): CN7 1* 2* 9*; CN15 4(ID)*; U13 C4(HW_TYP_1/PI5)* D4(HW_TYP_0/PI4)* H1(OSC_OUT/PH1)* R3(T_SW_DIR/PA7)*; U29 4(NC)*

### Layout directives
differential pair; rule Impedance Constraint [Min = 85.00    Max = 95.00    ]: USB_DEV_HS_CN_N, USB_DEV_HS_CN_P, USB_DEV_HS_N, USB_DEV_HS_P
rule Undefined; rule Matched Net Lengths [Tolerance = 0.2mm]; rule Impedance Constraint [Min = 85.00    Max = 95.00    ]: USB_DEV_HS_CN_N, USB_DEV_HS_CN_P, USB_DEV_HS_N, USB_DEV_HS_P

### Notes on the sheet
- Silkscreen = Reserved
- KEY

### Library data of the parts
C71 = MCD-00012: Capacitor, MLCC, 2.2uF, 10V, X5R, 10%, 0603, T=0,8mm; Manufacturer_Part_Number: CC0603KRX5R6BB225; Manufacturer: YAGEO; Alternate_Manufacturer_Part_Number: C0603C225K8PACTU; Alternate_Manufacturer: KEMET; BMS_Part_Number: 9142010; Part_Preference: Recommended; Provided_By: SUBCO; Component_Country_Of_Origin: China; ID: 2467; ShowFields: YES
C72 = MCD-00016: Capacitor, MLCC, 20pF, 50V, NPO, 5%, 0402, T=0,5mm; Manufacturer_Part_Number: CC0402JRNPO9BN200; Manufacturer: YAGEO; Part_Preference: Recommended; Provided_By: SUBCO; Component_Country_Of_Origin: China; ID: 2479; ShowFields: YES
C104 C108 = MCD-00006: as C98-C100 on sheet FDCAN
C115 = MCD-00205: Capacitor, MLCC, 100pF, 50V, NPO, 5%, 0402, T=0,5mm; Manufacturer_Part_Number: CC0402JRNPO9BN101; Manufacturer: YAGEO; Part_Preference: Recommended; Provided_By: SUBCO; Component_Country_Of_Origin: China; ID: 2658; ShowFields: YES
CN6 = MCD-00029: Header, 4x1, 2,54mm, VR, TH, Height 5.84mm/2.54mm; Manufacturer_Part_Number: TSW-104-07-G-S; Manufacturer: SAMTEC; Part_Type: Connector; Part_Preference: Recommended; Provided_By: SUBCO; Component_Country_Of_Origin: China, Costa Rica, Malaysia, United States, Vietnam; ID: 2487; Order_Code_RS: 161-2261; ShowFields: YES
CN7 = MCD-01226: Header 5x2, 1.27mm, Dual row, Straight, Surface mount, vertical male connector. 3.05mm lead. Mates with FFSD connector. Footprint compatible with FTSH-107-01-L-DV,-K,-A,-P,-ES (STDC14 MEDIUM); Manufacturer_Part_Number: FTSH-105-01-L-DV-K; Manufacturer: SAMTEC; Alternate_Manufacturer_Part_Number: P127B-2x05MGF-079-1A; Alternate_Manufacturer: JIUBABA; Part_Preference: Recommended; Partial_Alternate_Internal_Part_Number: MCD-02021, MCD-02956; Provided_By: SUBCO; Alternate_EMS: A; Component_Country_Of_Origin: China, Costa Rica, Malaysia, United States, Vietnam; ID: 3265; Order_Code_RS: 159-2332; ShowFields: YES
CN15 = MCD-00028: USB-MICRO-B, 0.65mm, RA, SMT, Bottom Mount,; Manufacturer_Part_Number: 1050170001; Manufacturer: MOLEX; Part_Type: Connector; Part_Preference: Recommended; Provided_By: SUBCO; Component_Country_Of_Origin: Unknown; ID: 2489; Order_Code_RS: 848-6764; ShowFields: YES
JP2 JP3 = MCD-00045: as JP4 on sheet FDCAN
LD6 = MCD-02402: LED Bicolor; Part_Type: Display; Manufacturer_Part_Number: 67-22SURSYGC/S530-A2/TR8; Manufacturer: EVERLIGHT; Full_Alternate_Internal_Part_Number: MCD-00051, MCD-02631; Part_Preference: Alternate; Alternate_EMS: C; ID: 4508; ShowFields: YES
R88 R97 R111 R146 = MCD-00067: Resistor, 100R, 0402, +/- 1%, 1/16W; Manufacturer_Part_Number: RC0402FR-07100RL; Manufacturer: YAGEO; Part_Preference: Recommended; Component_Country_Of_Origin: China; ID: 2527; ShowFields: YES
R89 = MCD-00185: Resistor,3K,0402,1%,1/16W; Manufacturer_Part_Number: RC0402FR-073KL; Manufacturer: YAGEO; Part_Preference: Recommended; Provided_By: SUBCO; Component_Country_Of_Origin: China; ID: 2682; ShowFields: YES
R103 R104 R106 R108 R110 R114 = MCD-00189: Resistor,22R,0402,1%,1/16W; Manufacturer_Part_Number: RC0402FR-0722RL; Manufacturer: YAGEO; Part_Preference: Recommended; Provided_By: SUBCO; Component_Country_Of_Origin: China; ID: 2677; ShowFields: YES
R107 = MCD-00055: Resistor,2K7,0402,1%,1/16W; Manufacturer_Part_Number: RC0402FR-072K7L; Manufacturer: YAGEO; Part_Preference: Recommended; Provided_By: SUBCO; Component_Country_Of_Origin: China; ID: 2535; ShowFields: YES
R109 R112 R113 = MCD-00065: Resistor,4K7,0402,1%,1/16W; Manufacturer_Part_Number: RC0402FR-074K7L; Manufacturer: YAGEO; Alternate_Manufacturer_Part_Number: RT0402FRE074K7L; Part_Preference: Recommended; Partial_Alternate_Internal_Part_Number: MCD-03300; Provided_By: SUBCO; Alternate_EMS: M; Component_Country_Of_Origin: China; ID: 2526; ShowFields: YES
R115 = MCD-00053: as R120 on sheet FDCAN
R130 R131 = MCD-00197: Resistor,330R,0603,1%,1/10W; Manufacturer_Part_Number: RC0603FR-07330RL; Manufacturer: YAGEO; BMS_Part_Number: 9129729; Part_Preference: Recommended; Provided_By: SUBCO; Component_Country_Of_Origin: China; ID: 2672; ShowFields: YES
TP3 = MCD-00074: Test Point 1mm; Part_Type: Misc; Part_Preference: Recommended; Initial_Board_Reference: MB1274; ID: 2518; ShowFields: YES
U13 = MCD-00596: STM32F723IEK  (STM32F7) BGA176; Part_Type: IC; Manufacturer_Part_Number: STM32F723IEK6; Manufacturer: STMICROELECTRONICS; BMS_Part_Number: 9175300; Manufacturer_HQ_COO: EU; Part_Preference: Recommended; Provided_By: SUBCO with ST control; Component_Country_Of_Origin: Philippines; ID: 3144; ShowFields: YES
U16 U18 = MCD-00136: Dual Transil array for ESD protection; Part_Type: Diode; Manufacturer: STMICROELECTRONICS; BMS_Part_Number: 9151112; Manufacturer_HQ_COO: EU; Part_Preference: Recommended; Provided_By: SUBCO with ST control; Component_Country_Of_Origin: China; ID: 2731; ShowFields: YES
U29 = MCD-00649: Common mode filter with ESD protection for USB 2.0 interface; Part_Type: Diode; Manufacturer: STMICROELECTRONICS; BMS_Part_Number: 9151138; Manufacturer_HQ_COO: EU; Part_Preference: Recommended; Provided_By: SUBCO with ST control; Component_Country_Of_Origin: China; ID: 3094; ShowFields: YES
U30 = MCD-00251: High power transient voltage suppressor, 7V breakdown; Part_Type: Diode; Manufacturer: STMICROELECTRONICS; BMS_Part_Number: 9179042; Manufacturer_HQ_COO: EU; Part_Preference: Recommended; Provided_By: SUBCO with ST control; Component_Country_Of_Origin: China; ID: 2618; ShowFields: YES
U34 = MCD-00170: ESD protection 6V1; Part_Type: Diode; Manufacturer: STMICROELECTRONICS; BMS_Part_Number: 9151132; Manufacturer_HQ_COO: EU; Part_Preference: Recommended; ECCN_US: EAR99; ECCN_EU: NEC; Provided_By: SUBCO with ST control; Component_Country_Of_Origin: China; ID: 2696; ShowFields: YES
X3 = MCD-00597: Oscillator 25Mhz, +-50ppm, Vcc:3.3V typ, square wave: [0.1Vcc;0.9Vcc], Enable pin, SMD; Part_Type: Crystal_Osc; Manufacturer_Part_Number: NZ2520SH-25MHZ-END4869C; Manufacturer: NDK; Alternate_Manufacturer_Part_Number: NZ2520SB 25MHz END4869B; BMS_Part_Number: 9157050; Part_Preference: Recommended; Provided_By: SUBCO; Component_Country_Of_Origin: Unknown; ID: 3148; ShowFields: YES

## Sheet STlink_V3E_PWR.SchDoc: ST-LINK/V3E-SWD Power Module
size A4; Date: Not used; ApprovedBy: Not used; CheckedBy: Not used; Author: Not used; CompanyName: STMicroelectronics; DrawnBy: Not used; Engineer: Not used; Organization: Not used; Address1: Not used; Address2: Not used; Address3: Not used; Address4: Not used; DocumentNumber: Not used; Revision: Not used; SheetNumber: 18; SheetTotal: 19
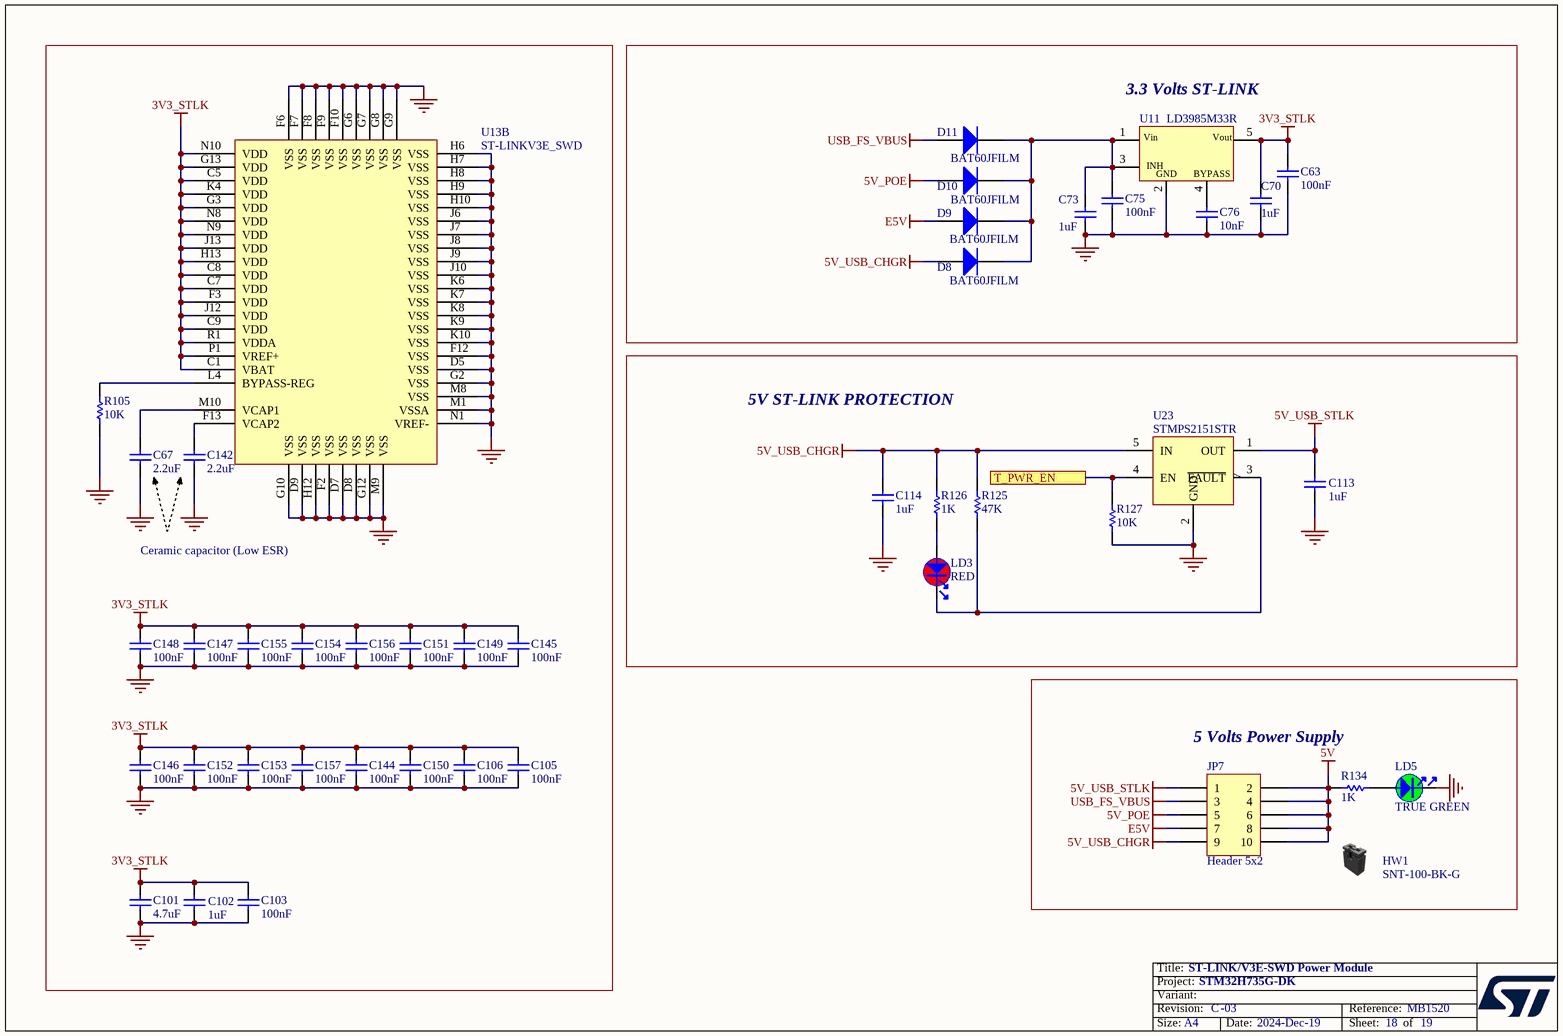
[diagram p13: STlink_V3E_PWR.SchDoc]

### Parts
C63  value 100nF  [C0402]  (hidden comment: Capacitor)
C67  value 2.2uF  [C1206_H1P15]  (hidden comment: Capacitor)
C70  value 1uF  [C0603]  (hidden comment: Capacitor)
C73  value 1uF  [C0603]  (hidden comment: Capacitor)
C75  value 100nF  [C0402]  (hidden comment: Capacitor)
C76  value 10nF  [C0402]  (hidden comment: Capacitor)
C101  value 4.7uF  [C0603]  (hidden comment: Capacitor)
C102  value 1uF  [C0603]  (hidden comment: Capacitor)
C103  value 100nF  [C0402]  (hidden comment: Capacitor)
C105  value 100nF  [C0402]  (hidden comment: Capacitor)
C106  value 100nF  [C0402]  (hidden comment: Capacitor)
C113  value 1uF  [C0603]  (hidden comment: Capacitor)
C114  value 1uF  [C0603]  (hidden comment: Capacitor)
C142  value 2.2uF  [C1206_H1P15]  (hidden comment: Capacitor)
C144  value 100nF  [C0402]  (hidden comment: Capacitor)
C145  value 100nF  [C0402]  (hidden comment: Capacitor)
C146  value 100nF  [C0402]  (hidden comment: Capacitor)
C147  value 100nF  [C0402]  (hidden comment: Capacitor)
C148  value 100nF  [C0402]  (hidden comment: Capacitor)
C149  value 100nF  [C0402]  (hidden comment: Capacitor)
C150  value 100nF  [C0402]  (hidden comment: Capacitor)
C151  value 100nF  [C0402]  (hidden comment: Capacitor)
C152  value 100nF  [C0402]  (hidden comment: Capacitor)
C153  value 100nF  [C0402]  (hidden comment: Capacitor)
C154  value 100nF  [C0402]  (hidden comment: Capacitor)
C155  value 100nF  [C0402]  (hidden comment: Capacitor)
C156  value 100nF  [C0402]  (hidden comment: Capacitor)
C157  value 100nF  [C0402]  (hidden comment: Capacitor)
D8  BAT60JFILM  [DIO_SOD323]
D9  BAT60JFILM  [DIO_SOD323]
D10  BAT60JFILM  [DIO_SOD323]
D11  BAT60JFILM  [DIO_SOD323]
HW1  value SNT-100-BK-G  (hidden comment: Shunt Black 2.54mm)  (mechanical)
JP7  Header 5x2  [CON_988-JIUBABA_PHFS25-12-10-G0B115-T-1]
LD3  value RED  [LED_0603_VISHAY_VLMS1300-GS08_RED_1A2K_H0P8]  (hidden comment: LED_red)
LD5  value TRUE GREEN  [LED_0603_VISHAY_VLMTG1300-GS08_GREEN_1A2K_H0P8]  (hidden comment: LED_green)
R105  value 10K  [R0402]  (hidden comment: Resistor)
R125  value 47K  [R0402]  (hidden comment: Resistor)
R126  value 1K  [R0402]  (hidden comment: Resistor)
R127  value 10K  [R0402]  (hidden comment: Resistor)
R134  value 1K  [R0603]  (hidden comment: Resistor)
U11  LD3985M33R  [REG_SOT23-5L]
U13  ST-LINKV3E_SWD  [ICC_UFBGA201_176+25_10X10_P065]  (part B of 2)
U23  STMPS2151STR  [MOS_SOT23-5L]

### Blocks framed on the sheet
Ceramic capacitor (Low ESR): C67 C101-C103 C105 C106 C142 C144-C157 R105 U13
3.3 Volts ST-LINK: C63 C70 C73 C75 C76 D8-D11 U11
5V ST-LINK PROTECTION: C113 C114 LD3 R125-R127 U23
5 Volts Power Supply: HW1 JP7 LD5 R134

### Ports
T_PWR_EN

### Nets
3V3_STLK: C63.2 C70.2 C101.2 C102.2 C103.2 C105.2 C106.2 C144.2 C145.2 C146.2 C147.2 C148.2 C149.2 C150.2 C151.2 C152.2 C153.2 C154.2 C155.2 C156.2 C157.2 U11.5(Vout) U13.C1(VBAT) U13.C5(VDD) U13.C7(VDD) U13.C8(VDD) U13.C9(VDD) U13.F3(VDD) U13.G3(VDD) U13.G13(VDD) U13.H13(VDD) U13.J12(VDD) U13.J13(VDD) U13.K4(VDD) U13.N8(VDD) U13.N9(VDD) U13.N10(VDD) U13.P1(VREF+) U13.R1(VDDA)
5V: JP7.2 JP7.4 JP7.6 JP7.8 JP7.10 R134.1
5V_POE: D10.1(A) JP7.5
5V_USB_CHGR: C114.2 D8.1(A) JP7.9 R125.2 R126.2 U23.5(IN)
5V_USB_STLK: C113.2 JP7.1 U23.1(OUT)
E5V: D9.1(A) JP7.7
GND: C63.1 C67.1 C70.1 C73.2 C75.1 C76.1 C101.1 C102.1 C103.1 C105.1 C106.1 C113.1 C114.1 C142.1 C144.1 C145.1 C146.1 C147.1 C148.1 C149.1 C150.1 C151.1 C152.1 C153.1 C154.1 C155.1 C156.1 C157.1 LD5.2 R105.1 R127.2 U11.2(GND) U13.D5(VSS) U13.D7(VSS) U13.D8(VSS) U13.D9(VSS) U13.F2(VSS) U13.F6(VSS) U13.F7(VSS) U13.F8(VSS) U13.F9(VSS) U13.F10(VSS) U13.F12(VSS) U13.G2(VSS) U13.G6(VSS) U13.G7(VSS) U13.G8(VSS) U13.G9(VSS) U13.G10(VSS) U13.G12(VSS) U13.H6(VSS) U13.H7(VSS) U13.H8(VSS) U13.H9(VSS) U13.H10(VSS) U13.H12(VSS) U13.J6(VSS) U13.J7(VSS) U13.J8(VSS) U13.J9(VSS) U13.J10(VSS) U13.K6(VSS) U13.K7(VSS) U13.K8(VSS) U13.K9(VSS) U13.K10(VSS) U13.M1(VSSA) U13.M8(VSS) U13.M9(VSS) U13.N1(VREF-) U23.2(GND)  [project net POE7]
USB_FS_VBUS: D11.1(A) JP7.3
T_PWR_EN: R127.1 U23.4(EN) ; port T_PWR_EN
NetC67_2: C67.2 U13.M10(VCAP1)
NetC73_1: C73.1 C75.2 D8.2(K) D9.2(K) D10.2(K) D11.2(K) U11.1(Vin) U11.3(CE)
NetC76_2: C76.2 U11.4(BYPASS)
NetC142_2: C142.2 U13.F13(VCAP2)
NetLD3_1: LD3.1 R126.1
NetLD3_2: LD3.2 R125.1 U23.3(~{FAULT})
NetLD5_1: LD5.1 R134.2
NetR105_2: R105.2 U13.L4(BYPASS-REG)

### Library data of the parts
C63 C75 C103 C105 C106 C144-C157 = MCD-00006: as C98-C100 on sheet FDCAN
C67 C142 = MCD-00008: Capacitor, MLCC, 2.2uF, 16V, X7R, 10%, 1206, T=1,15mm; Manufacturer_Part_Number: CC1206KKX7R7BB225; Manufacturer: YAGEO; Alternate_Manufacturer_Part_Number: C1206C225K4RAC; Alternate_Manufacturer: KEMET; Part_Preference: Recommended; Provided_By: SUBCO; Component_Country_Of_Origin: China; ID: 2472; Order_Code_RS: 669-8454; ShowFields: YES
C70 C102 C113 C114 = MCD-00010: Capacitor, MLCC, 1uF, 16V, X5R, 10%, 0603, T=0,8mm; Manufacturer_Part_Number: CC0603KRX5R7BB105; Manufacturer: YAGEO; Part_Preference: Recommended; Provided_By: SUBCO; Component_Country_Of_Origin: China; ID: 2470; ShowFields: YES
C73 = MCD-00238: Capacitor, MLCC, 1uF, 6V3, X5R, 10%, 0603, T=0,8mm; Manufacturer_Part_Number: CC0603KRX5R5BB105; Manufacturer: YAGEO; Part_Preference: Recommended; Provided_By: SUBCO; Component_Country_Of_Origin: China; ID: 2629; ShowFields: YES
C76 = MCD-00011: Capacitor, MLCC, 10nF, 16V, X7R, 10%, 0402, T=0.5mm; Manufacturer_Part_Number: CC0402KRX7R7BB103; Manufacturer: YAGEO; Part_Preference: Recommended; Provided_By: SUBCO; Component_Country_Of_Origin: China; ID: 2469; Order_Code_RS: 669-8688; ShowFields: YES
C101 = MCD-00009: Capacitor, MLCC, 4.7uF, 16V, X5R, 10%, 0603, T=0.8mm; Manufacturer_Part_Number: CC0603KRX5R7BB475; Manufacturer: YAGEO; Part_Preference: Recommended; Partial_Alternate_Internal_Part_Number: MCD-03565; Provided_By: SUBCO; Alternate_EMS: A; Component_Country_Of_Origin: China; ID: 2471; ShowFields: YES
D8-D11 = MCD-00034: Manufacturer: STMICROELECTRONICS; Part_Type: Diode; BMS_Part_Number: 9151097; Manufacturer_HQ_COO: EU; Part_Preference: Recommended; Provided_By: SUBCO with ST control; Component_Country_Of_Origin: China; ID: 2483; ShowFields: YES
HW1 = MCD-00043: Jumper, 2.54mm, Black, 4.3A, 6.1mm, 5mR; Manufacturer: SAMTEC; Part_Type: Misc; Full_Alternate_Internal_Part_Number: MCD-02388; Manufacturer_HQ_COO: Unknown; Part_Preference: Recommended; Partial_Alternate_Internal_Part_Number: MCD-01849, MCD-01864; Alternate_EMS: A; Component_Country_Of_Origin: China, Costa Rica, Malaysia, USA, Vietnam; ID: 2551; Order_Code_RS: 158-7784; ShowFields: YES
JP7 = MCD-00312: Header, 5x2, 2.54mm, VR, TH, Height 6mm/3mm; Part_Type: Connector; Manufacturer_Part_Number: PHFS25-12-10-G0B115-T-1; Manufacturer: JIUBABA; Part_Preference: Alternate; Provided_By: SUBCO; Alternate_EMS: A; Component_Country_Of_Origin: Unknown; ID: 2560; ShowFields: YES
LD3 = MCD-00587: LED Red, 0603 SMD, 2V Forward Voltage; Part_Type: Display; Manufacturer_Part_Number: VLMS1300-GS08; Manufacturer: VISHAY; Alternate_Manufacturer_Part_Number: LS Q976-NR-1; Alternate_Manufacturer: OSRAM OPTO SEMICONDUCTORS; Full_Alternate_Internal_Part_Number: MCD-02401; Part_Preference: Recommended; Provided_By: SUBCO; Component_Country_Of_Origin: China; ID: 3154; ShowFields: YES
LD5 = MCD-00589: LED Green, 0603 SMD, Fw Voltage = 2.8V - 3.6V; Part_Type: Display; Manufacturer_Part_Number: VLMTG1300-GS08; Manufacturer: VISHAY; Alternate_Manufacturer_Part_Number: LG Q396-PS-35; Alternate_Manufacturer: OSRAM OPTO SEMICONDUCTORS; Part_Preference: Recommended; Order_Code_RS: 7730452; Provided_By: SUBCO; Component_Country_Of_Origin: China; ID: 3157; ShowFields: YES
R105 R127 = MCD-00053: as R120 on sheet FDCAN
R125 = MCD-00063: Resistor,47K,0402,1%,1/16W; Manufacturer_Part_Number: RC0402FR-0747KL; Manufacturer: YAGEO; Part_Preference: Recommended; Provided_By: SUBCO; Component_Country_Of_Origin: China; ID: 2528; ShowFields: YES
R126 = MCD-00061: Resistor,1K,0402,1%,1/16W; Manufacturer_Part_Number: RC0402FR-071KL; Manufacturer: YAGEO; Part_Preference: Recommended; Provided_By: SUBCO; Component_Country_Of_Origin: China; ID: 2532; ShowFields: YES
R134 = MCD-00070: as R22 on sheet PoE
U11 = MCD-00086: Ultra low drop-low noise BiCMOS voltage, regulators low ESR capacitors compatible; Manufacturer: STMICROELECTRONICS; Part_Type: IC; BMS_Part_Number: 9176161; Manufacturer_HQ_COO: EU; Part_Preference: Recommended; Provided_By: SUBCO with ST control; Component_Country_Of_Origin: China; ID: 2506; ShowFields: YES
U13 = MCD-00596: as U13 on sheet STlink_V3E_Module
U23 = MCD-00159: 500mA, Enhanced single channel power switches with active high enable pin; Part_Type: IC; Manufacturer: STMICROELECTRONICS; Alternate_Manufacturer_Part_Number: TPS2051C; Alternate_Manufacturer: TEXAS INSTRUMENTS; BMS_Part_Number: 9159009; Manufacturer_HQ_COO: EU; Part_Preference: Recommended; Provided_By: SUBCO with ST control; Component_Country_Of_Origin: Malaysia; ID: 2708; Order_Code_RS: 880-5415; ShowFields: YES

## Sheet HW_Mechanical_Parts.SchDoc: HW Mechanical parts
size A4; Date: Not used; ApprovedBy: Not used; CheckedBy: Not used; Author: Not used; CompanyName: STMicroelectronics; DrawnBy: Not used; Engineer: Not used; Organization: Not used; Address1: Not used; Address2: Not used; Address3: Not used; Address4: Not used; DocumentNumber: Not used; Revision: Not used; SheetNumber: 19; SheetTotal: 19
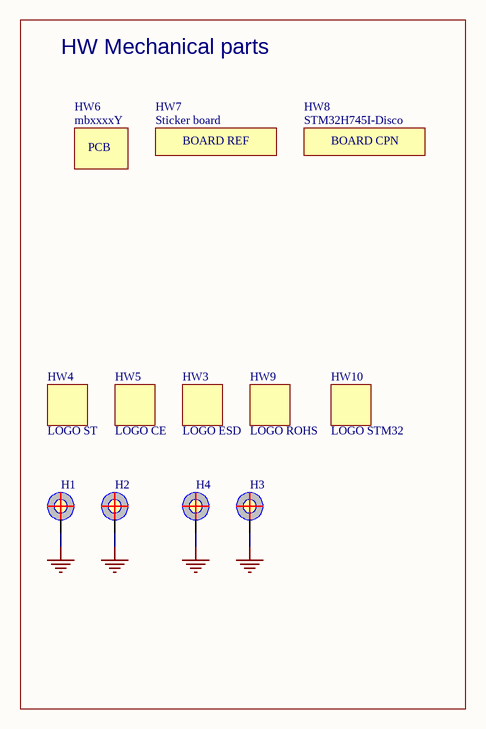
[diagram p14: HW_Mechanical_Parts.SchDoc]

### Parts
H1  POSITION HOLE  [PTH_350_700]  (value not drawn)  (no BOM)
H2  POSITION HOLE  [PTH_350_700]  (value not drawn)  (no BOM)
H3  POSITION HOLE  [PTH_350_700]  (value not drawn)  (no BOM)
H4  POSITION HOLE  [PTH_350_700]  (value not drawn)  (no BOM)
HW3  value LOGO ESD  [LOGO_MAIN_1]  (hidden comment: Logo)  (no BOM)
HW4  value LOGO ST  [LOGO_ST]  (hidden comment: Logo)  (no BOM)
HW5  value LOGO CE  [LOGO_CE]  (hidden comment: Logo)  (no BOM)
HW6  value mbxxxxY  (hidden comment: PCB)  (no BOM)
HW7  value Sticker board  [STICKER_25X9]  (hidden comment: STICKER_BOARD_REF)  (no BOM)
HW8  value STM32H745I-Disco  (hidden comment: STICKER_BOARD_CPN)  (no BOM)
HW9  value LOGO ROHS  [LOGO_ROHS]  (hidden comment: Logo)  (no BOM)
HW10  value LOGO STM32  [LOGO_STM32]  (hidden comment: Logo)  (no BOM)

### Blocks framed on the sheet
HW Mechanical parts: H1-H4 HW3-HW10

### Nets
GND: H1.1 H2.1 H3.1 H4.1  [project net POE7]

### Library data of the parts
H1-H4 = MCD-00328: POSITION HOLE C7D3R5; Part_Type: Misc; Part_Preference: Recommended; ID: 2950; ShowFields: YES
HW3 = MCD-00627: Hand ESD logo footprint for PCB; Part_Type: Misc; Part_Preference: Forbidden; ID: 3114; ShowFields: YES
HW4 = MCD-00625: STMicroelectronics logo footprint for PCB; Part_Type: Misc; Part_Preference: Forbidden; ID: 3117; ShowFields: YES
HW5 = MCD-00626: CE logo footprint for PCB; Part_Type: Misc; Part_Preference: Forbidden; ID: 3116; ShowFields: YES
HW6 = MCD-00036: PCB, xxxx for PCB ref, Y for revision; Part_Type: Misc; Part_Preference: Forbidden; Provided_By: SUBCO; ID: 2481; ShowFields: YES
HW7 = MCD-00235: Sticker to mention board reference + serial number; Part_Type: Misc; Part_Preference: Recommended; Provided_By: SUBCO; ID: 2632; ShowFields: YES
HW8 = MCD-00549: Sticker to mention board CPN code; Part_Type: Mechanical; Provided_By: Subcon; Initial_Board_Reference: mb1319
HW9 = MCD-00628: ROHS logo footprint for PCB; Part_Type: Misc; Part_Preference: Forbidden; ID: 3120; ShowFields: YES
HW10 = MCD-00629: STM32 logo footprint for PCB; Part_Type: Misc; Part_Preference: Forbidden; ID: 3119; ShowFields: YES

## Sheet OCSPI.SchDoc: OCSPI
size A4; Date: Not used; ApprovedBy: Not used; CheckedBy: Not used; Author: Not used; CompanyName: STMicroelectronics; DrawnBy: Not used; Engineer: Not used; Organization: Not used; Address1: Not used; Address2: Not used; Address3: Not used; Address4: Not used; DocumentNumber: Not used; Revision: Not used; SheetNumber: 9; SheetTotal: 19
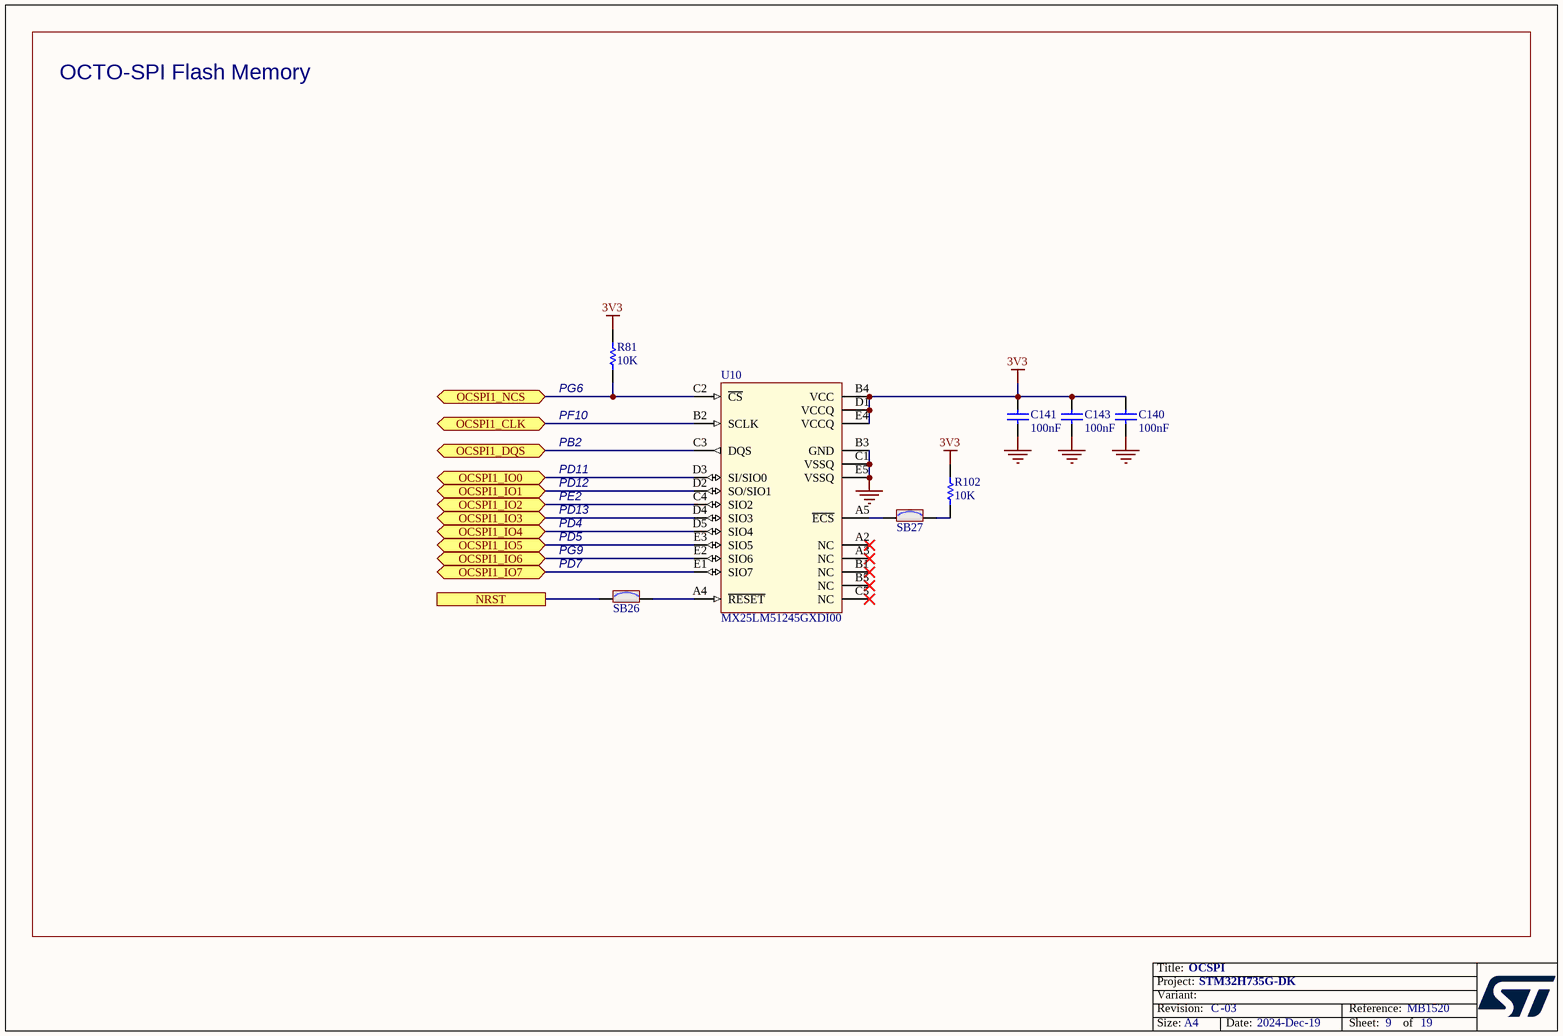
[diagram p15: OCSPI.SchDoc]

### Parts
C140  value 100nF  [C0402]  (hidden comment: Capacitor)
C141  value 100nF  [C0402]  (hidden comment: Capacitor)
C143  value 100nF  [C0402]  (hidden comment: Capacitor)
R81  value 10K  [R0402]  (hidden comment: Resistor)
R102  value 10K  [R0402]  (hidden comment: Resistor)
SB26  SB_ON  [SOLDER-BRIDGE_R0603-0R]  (value not drawn)
SB27  SB_ON  [SOLDER-BRIDGE_R0603-0R]  (value not drawn)
U10  MX25LM51245GXDI00  [ICC_BGA24_5X5-BALL-ARRAY_6X8_P1]

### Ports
NRST, OCSPI1_CLK (bidir), OCSPI1_DQS (bidir), OCSPI1_IO0 (bidir), OCSPI1_IO1 (bidir), OCSPI1_IO2 (bidir), OCSPI1_IO3 (bidir), OCSPI1_IO4 (bidir), OCSPI1_IO5 (bidir), OCSPI1_IO6 (bidir), OCSPI1_IO7 (bidir), OCSPI1_NCS (bidir)

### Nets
3V3: C140.2 C141.2 C143.2 R81.2 R102.2 U10.B4(VCC) U10.D1(VCCQ) U10.E4(VCCQ)
GND: C140.1 C141.1 C143.1 U10.B3(GND) U10.C1(VSSQ) U10.E5(VSSQ)  [project net POE7]
OCSPI1_CLK: U10.B2(SCLK) ; port OCSPI1_CLK
OCSPI1_DQS: U10.C3(DQS) ; port OCSPI1_DQS
OCSPI1_IO0: U10.D3(SI/SIO0) ; port OCSPI1_IO0
OCSPI1_IO1: U10.D2(SO/SIO1) ; port OCSPI1_IO1
OCSPI1_IO2: U10.C4(SIO2) ; port OCSPI1_IO2
OCSPI1_IO3: U10.D4(SIO3) ; port OCSPI1_IO3
OCSPI1_IO4: U10.D5(SIO4) ; port OCSPI1_IO4
OCSPI1_IO5: U10.E3(SIO5) ; port OCSPI1_IO5
OCSPI1_IO6: U10.E2(SIO6) ; port OCSPI1_IO6
OCSPI1_IO7: U10.E1(SIO7) ; port OCSPI1_IO7
OCSPI1_NCS: R81.1 U10.C2(~{CS}) ; port OCSPI1_NCS
RESET: SB26.1 ; port NRST
NetR102_1: R102.1 SB27.2
NetSB26_2: SB26.2 U10.A4(~{RESET})
NetSB27_1: SB27.1 U10.A5(~{ECS})

Not connected (* = marked no-connect by the designer): U10 A2(NC)* A3(NC)* B1(NC)* B5(NC)* C5(NC)*

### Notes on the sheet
- OCTO-SPI Flash Memory
- (near R81) PG6
- (near R81) PF10
- PB2
- PD11
- PD12
- PE2
- PD13
- PD4
- PD5
- PG9
- (near SB26) PD7

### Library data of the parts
C140 C141 C143 = MCD-00006: as C98-C100 on sheet FDCAN
R81 R102 = MCD-00053: Resistor,10K,0402,1%,1/16W; Manufacturer_Part_Number: RC0402FR-0710KL; Manufacturer: YAGEO; BMS_Part_Number: 9131590; Part_Preference: Recommended; ECCN_US: EAR99; ECCN_EU: NEC; Provided_By: SUBCO; Component_Country_Of_Origin: China; ID: 2539; ShowFields: YES
SB26 SB27 = MCD-00071: Solder Bridge ON; Part_Type: Misc; Manufacturer_Part_Number: RC0603JR-070RL; Manufacturer: YAGEO; Part_Preference: Recommended; Provided_By: SUBCO; ID: 2521; ShowFields: YES
U10 = MCD-00246: Memory,Octo-SPI-NOR,512Mb,2048x16,133MHz,3V,DTR,BGA24, CMOS MXSMIO; Part_Type: IC; Manufacturer: MACRONIX; Part_Preference: Recommended; ECCN_US: tbd; Provided_By: SUBCO; Component_Country_Of_Origin: Unknown; ID: 2623; ShowFields: YES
